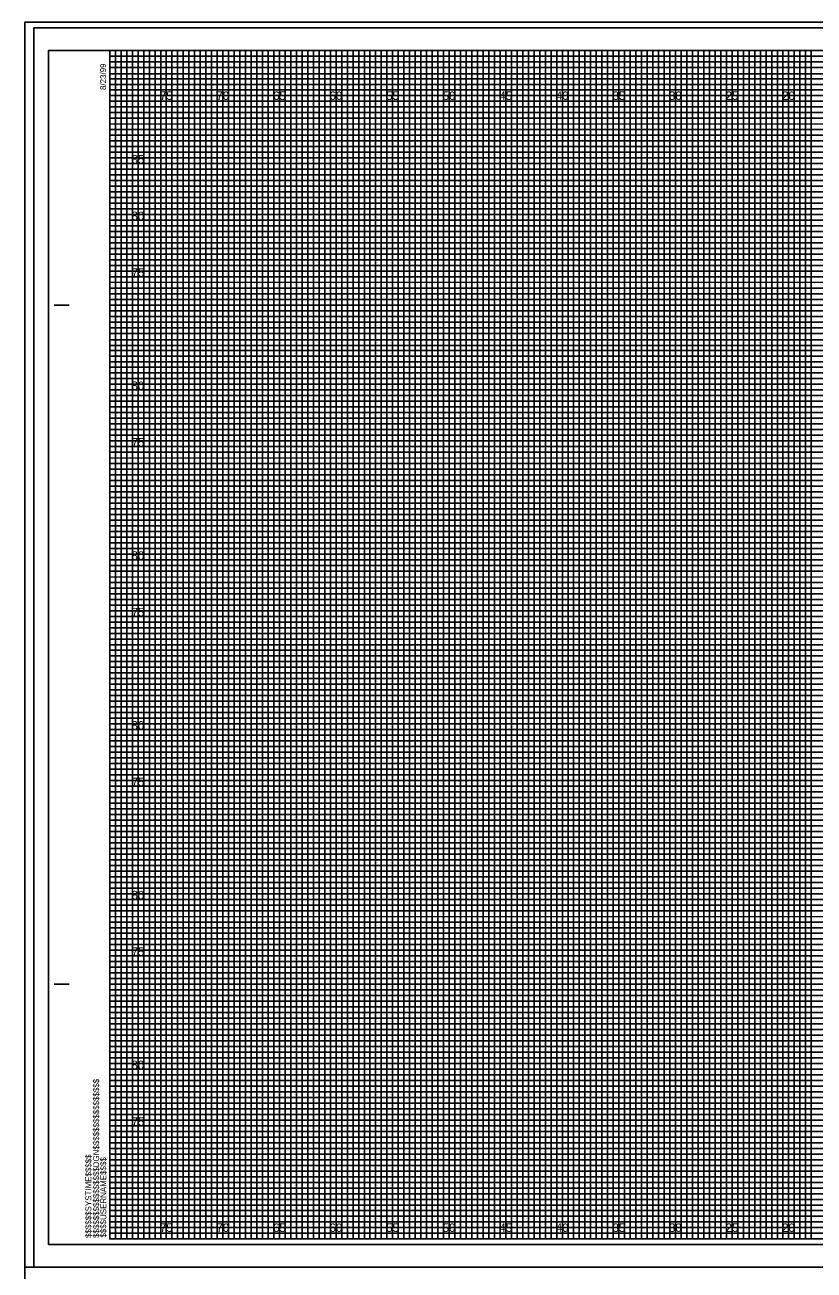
# Model space of a CAD drawing. Extents: x -8 to 533, y -20 to 768.
# Drawn here: x -7.5 to 62.2, y 217.2 to 327.2 of the extents above; entities that cross this region are included whole.
import ezdxf

# ---------------------------------------------------------------- set-up
doc = ezdxf.new("R2010")
doc.units = 0
for name, color, linetype in [('Prop XS Elevation Labels', 7, 'Continuous'), ('Prop XS Offset Labels', 7, 'Continuous'), ('Sheet Cross Section CELL', 7, 'Continuous'), ('Sheet Cross Section Grid Major CELL', 7, 'Continuous'), ('Sheet Cross Section Grid Middle CELL', 7, 'Continuous'), ('Sheet Cross Section Grid Minor 1 CELL', 7, 'Continuous'), ('Sheet Cross Section Grid Minor 2 CELL', 7, 'Continuous'), ('Sheet Cutting Line CELL', 7, 'Continuous'), ('Sheet DOT Grid CELL', 7, 'Continuous'), ('Sheet Plot Border Inside CELL', 7, 'Continuous'), ('Sheet Plot Border Outside CELL', 7, 'Continuous'), ('WEI Plot Border', 7, 'Continuous')]:
    doc.layers.add(name, color=color, linetype=linetype)

msp = doc.modelspace()

# ---------------------------------------------------------------- linework, layer by layer
at = {"layer": 'Sheet Cross Section CELL'}
for p, q in [((-4.9, 302.5), (-3.65, 302.5)), ((-4.85, 302.5), (-3.6, 302.5)), ((-4.9, 242.5), (-3.65, 242.5)), ((-4.85, 242.5), (-3.6, 242.5)), ((0, 220), (0, 220)), ((0, 220), (0, 220)), ((0, 220), (0, 220)), ((0, 220), (0, 220)), ((0, 220), (0, 220)), ((0, 220), (0, 220)), ((0, 220), (0, 220))]:
    msp.add_line(p, q, dxfattribs=at)
msp.add_lwpolyline([(160, 325), (0, 325), (0, 220), (160, 220)], close=True, dxfattribs=at)
at = {"layer": 'Sheet Cross Section Grid Major CELL'}
for p, q in [((5, 325), (0, 325)), ((5, 220), (5, 325)), ((15, 325), (10, 325)), ((10, 325), (10, 220)), ((15, 220), (15, 325)), ((25, 325), (20, 325)), ((20, 325), (20, 220)), ((25, 220), (25, 325)), ((35, 325), (30, 325)), ((30, 325), (30, 220)), ((35, 220), (35, 325)), ((45, 325), (40, 325)), ((40, 325), (40, 220)), ((45, 220), (45, 325)), ((55, 325), (50, 325)), ((50, 325), (50, 220)), ((55, 220), (55, 325)), ((65, 325), (60, 325)), ((60, 325), (60, 220)), ((10, 220), (5, 220)), ((20, 220), (15, 220)), ((30, 220), (25, 220)), ((40, 220), (35, 220)), ((50, 220), (45, 220)), ((60, 220), (55, 220))]:
    msp.add_line(p, q, dxfattribs=at)
for points in [[(0, 320), (160, 320), (160, 315), (0, 315)], [(0, 310), (160, 310), (160, 305), (0, 305)], [(0, 300), (160, 300), (160, 295), (0, 295)], [(0, 290), (160, 290), (160, 285), (0, 285)], [(0, 280), (160, 280), (160, 275), (0, 275)], [(0, 270), (160, 270), (160, 265), (0, 265)], [(0, 260), (160, 260), (160, 255), (0, 255)], [(0, 250), (160, 250), (160, 245), (0, 245)], [(0, 240), (160, 240), (160, 235), (0, 235)], [(0, 230), (160, 230), (160, 225), (0, 225)]]:
    msp.add_lwpolyline(points, dxfattribs=at)
at = {"layer": 'Sheet Cross Section Grid Middle CELL'}
for points in [[(0, 325), (2.5, 325), (2.5, 220), (7.5, 220), (7.5, 325), (12.5, 325), (12.5, 220), (17.5, 220), (17.5, 325), (22.5, 325), (22.5, 220), (27.5, 220), (27.5, 325), (32.5, 325), (32.5, 220), (37.5, 220), (37.5, 325), (42.5, 325), (42.5, 220), (47.5, 220), (47.5, 325), (52.5, 325), (52.5, 220), (57.5, 220), (57.5, 325), (62.5, 325)], [(0, 322.5), (137.5, 322.5)], [(0, 312.5), (160, 312.5), (160, 317.5), (0, 317.5)], [(0, 302.5), (160, 302.5), (160, 307.5), (0, 307.5)], [(0, 292.5), (160, 292.5), (160, 297.5), (0, 297.5)], [(0, 282.5), (160, 282.5), (160, 287.5), (0, 287.5)], [(0, 272.5), (160, 272.5), (160, 277.5), (0, 277.5)], [(0, 262.5), (160, 262.5), (160, 267.5), (0, 267.5)], [(0, 252.5), (160, 252.5), (160, 257.5), (0, 257.5)], [(0, 242.5), (160, 242.5), (160, 247.5), (0, 247.5)], [(0, 232.5), (160, 232.5), (160, 237.5), (0, 237.5)], [(0, 222.5), (160, 222.5), (160, 227.5), (0, 227.5)]]:
    msp.add_lwpolyline(points, dxfattribs=at)
at = {"layer": 'Sheet Cross Section Grid Minor 1 CELL'}
for p, q in [((0, 324.5), (130, 324.5)), ((130, 323.99), (0, 323.99)), ((0, 323.99), (0, 323.5)), ((0, 323.5), (130, 323.5)), ((130, 322.94), (0, 322.94)), ((0, 322.94), (0, 322)), ((0, 322), (160, 322))]:
    msp.add_line(p, q, dxfattribs=at)
for points in [[(0, 321.5), (135, 321.5), (160, 321.5), (160, 321), (0, 321)], [(0, 320.5), (160, 320.5), (160, 319.5), (0, 319.5)], [(0, 319), (160, 319), (160, 318.5), (0, 318.49)], [(0, 318), (160, 318), (160, 317), (0, 317)], [(0, 316.5), (160, 316.5), (160, 316), (0, 316)], [(0, 315.5), (160, 315.5), (160, 314.5), (0, 314.5)], [(0, 314), (160, 314), (160, 313.5), (0, 313.5)], [(0, 313), (160, 313), (160, 312), (0, 312)], [(0, 311.5), (160, 311.5), (160, 311), (0, 311)], [(0, 310.5), (160, 310.5), (160, 309.5), (0, 309.5)], [(0, 309), (160, 309), (160, 308.5), (0, 308.5)], [(0, 308), (160, 308), (160, 306.98), (160, 306.5), (160, 306), (0, 306)], [(0, 307), (160, 307), (160, 306.5), (0, 306.5)], [(0, 305.5), (160, 305.5), (160, 304.5), (0, 304.51)], [(0, 304.51), (160, 304.5), (160, 304), (0, 304)], [(0, 303.5), (160, 303.5), (160, 303), (0, 303)], [(0, 302), (160, 302), (160, 301.5), (0, 301.5)], [(0, 301), (160, 301), (160, 300.5), (0, 300.5)], [(-0.04, 299.44), (160, 299.44), (160, 298.94), (-0.04, 298.94)], [(0, 298.5), (160, 298.5), (160, 298), (0, 298)], [(0, 297), (160, 297), (160, 296.5), (0, 296.5)], [(0, 296), (160, 296), (160, 295.5), (0, 295.5)], [(0, 294.5), (160, 294.5), (160, 294), (0, 294)], [(0, 293.5), (160, 293.5), (160, 293), (0, 293)], [(0, 292), (160, 292), (160, 291.5), (0, 291.5)], [(0, 291), (160, 291), (160, 290.5), (0, 290.5)], [(0, 289.5), (160, 289.5), (160, 288.99), (0, 289)], [(0, 288.5), (160, 288.5), (160, 288), (0, 288)], [(0, 287), (160, 287), (160, 286.5), (0, 286.5)], [(0, 286), (160, 286), (160, 285.5), (0, 285.5)], [(0, 284.5), (160, 284.5), (160, 284), (0, 284)], [(0, 283.5), (160, 283.5), (160, 283), (0, 283)], [(0, 282), (160, 282), (160, 281.5), (0, 281.5)], [(0, 281), (160, 281), (160, 280.5), (0, 280.5)], [(0, 279.5), (160, 279.5), (160, 279), (0, 279)], [(0, 278.5), (160.03, 278.45), (160, 278), (0, 278)], [(0, 277), (160, 277), (160, 276.5), (0, 276.5)], [(0, 276), (160, 276), (160, 275.5), (0, 275.5)], [(0, 274.5), (160, 274.5), (160, 274), (0, 274)], [(0, 273.5), (160, 273.5), (160, 273), (0, 273)], [(0, 272), (160, 272), (160, 271.5), (0, 271.5)], [(0, 271), (160, 271), (160, 270.5), (0, 270.5)], [(0, 269.5), (160, 269.5), (160, 269), (0, 269)], [(0, 268.5), (160, 268.5), (160, 268), (0, 268)], [(0, 267), (160, 267), (160, 266.5), (0, 266.5)], [(0, 266), (160, 266), (160, 265.5), (0, 265.5)], [(0, 264.5), (160, 264.5), (160, 264), (0, 264)], [(0, 263.5), (160, 263.5), (160, 263), (0, 263)], [(0, 262), (160, 262), (160, 261.5), (0, 261.5)], [(0, 261), (160, 261), (160, 260.5), (0, 260.5)], [(0, 259.5), (160, 259.5), (160, 258.99), (0, 259)], [(0, 258.5), (160, 258.5), (160, 258), (0, 258)], [(0, 257), (160, 257), (160, 256.5), (0, 256.5)], [(0, 256), (160, 256), (160, 255.5), (0, 255.5)], [(0, 254.5), (160, 254.5), (160, 254), (0, 254)], [(0, 253.5), (160, 253.5), (160, 253), (0, 253)], [(0, 252), (160, 252), (160, 251.5), (0, 251.5)], [(0, 251), (160, 251), (160, 250.5), (0, 250.5)], [(0, 249.5), (160, 249.5), (160, 249), (0, 249)], [(0, 248.5), (160.03, 248.46), (160, 248), (0, 248)], [(0, 247), (160, 247), (160, 246.5), (0, 246.5)], [(0, 246), (160, 246), (160, 245.5), (0, 245.5)], [(0, 244.5), (160, 244.5), (160, 244), (0, 244)], [(0, 243.5), (160, 243.5), (160, 243), (0, 243)], [(0, 242), (160, 242), (160, 241.5), (0, 241.5)], [(0, 241), (160, 241), (160, 240.5), (0, 240.5)], [(0, 239.5), (160, 239.5), (160, 239), (0, 239)], [(0, 238.5), (160, 238.5), (160, 238), (0, 238)], [(0, 237), (160, 237), (160, 236.5), (0, 236.5)], [(0, 236), (160, 236), (160, 235.5), (0, 235.5)], [(0, 234.5), (160, 234.5), (160, 234), (0, 234)], [(0, 233.5), (160, 233.5), (160, 233), (0, 233)], [(0, 232), (160, 232), (160, 231.5), (0, 231.5)], [(0, 231), (160, 231), (160, 230.5), (0, 230.5)], [(0, 229.5), (160, 229.5), (160, 229), (0, 229)], [(0, 228.5), (160, 228.5), (160, 228), (0, 228)], [(0, 227), (160, 227), (160, 226.5), (0, 226.5)], [(0, 226), (160, 226), (160, 225.5), (0, 225.5)], [(0, 224.5), (160, 224.5), (160, 224), (0, 224)], [(0, 223.5), (160, 223.5), (160, 223), (0, 223)], [(0, 222), (160, 222), (160, 221.5), (0, 221.5)], [(0, 221), (160, 221), (160, 220.5), (0, 220.5)]]:
    msp.add_lwpolyline(points, dxfattribs=at)
at = {"layer": 'Sheet Cross Section Grid Minor 2 CELL'}
for points in [[(0, 220), (0.5, 220), (0.5, 325), (1, 325), (1, 220)], [(1, 220), (1.5, 220), (1.5, 325), (2, 325), (2, 220)], [(2.5, 220), (3, 220), (3, 325), (3.5, 325), (3.5, 220)], [(3.5, 220), (4, 220), (4, 325), (4.5, 325), (4.5, 220)], [(5, 220), (5.5, 220), (5.5, 325), (6, 325), (6, 220)], [(6, 220), (6.5, 220), (6.5, 325), (7, 325), (7, 220)], [(7.5, 220), (8, 220), (8, 325), (8.5, 325), (8.5, 220)], [(8.5, 220), (9, 220), (9, 325), (9.5, 325), (9.5, 220)], [(10, 220), (10.5, 220), (10.5, 325), (11, 325), (11, 220)], [(11, 220), (11.5, 220), (11.5, 325), (12, 325), (12, 220)], [(12.5, 220), (13, 220), (13, 325), (13.5, 325), (13.5, 220)], [(13.5, 220), (14, 220), (14, 325), (14.5, 325), (14.5, 220)], [(15, 220), (15.5, 220), (15.5, 325), (16, 325), (16, 220)], [(16, 220), (16.5, 220), (16.5, 325), (17, 325), (17, 220)], [(17.5, 220), (18, 220), (18, 325), (18.5, 325), (18.5, 220)], [(18.5, 220), (19, 220), (19, 325), (19.5, 325), (19.5, 220)], [(20, 220), (20.5, 220), (20.5, 325), (21, 325), (21, 220)], [(21, 220), (21.5, 220), (21.5, 325), (22, 325), (22, 220)], [(22.5, 220), (23, 220), (23, 325), (23.5, 325), (23.5, 220)], [(23.5, 220), (24, 220), (24, 325), (24.5, 325), (24.5, 220)], [(25, 220), (25.5, 220), (25.5, 325), (26, 325), (26, 220)], [(26, 220), (26.5, 220), (26.5, 325), (27, 325), (27, 220)], [(27.5, 220), (28, 220), (28, 325), (28.5, 325), (28.5, 220)], [(28.5, 220), (29, 220), (29, 325), (29.5, 325), (29.5, 220)], [(30, 220), (30.5, 220), (30.5, 325), (31, 325), (31, 220)], [(31, 220), (31.5, 220), (31.5, 325), (32, 325), (32, 220)], [(32.5, 220), (33, 220), (33, 325), (33.5, 325), (33.5, 220)], [(33.5, 220), (34, 220), (34, 325), (34.5, 325), (34.5, 220)], [(35, 220), (35.5, 220), (35.5, 325), (36, 325), (36, 220)], [(36, 220), (36.5, 220), (36.5, 325), (37, 325), (37, 220)], [(37.5, 220), (38, 220), (38, 325), (38.5, 325), (38.5, 220)], [(38.5, 220), (39, 220), (39, 325), (39.5, 325), (39.5, 220)], [(40, 220), (40.5, 220), (40.5, 325), (41, 325), (41, 220)], [(41, 220), (41.5, 220), (41.5, 325), (42, 325), (42, 220)], [(42.5, 220), (43, 220), (43, 325), (43.5, 325), (43.5, 220)], [(43.5, 220), (44, 220), (44, 325), (44.5, 325), (44.5, 220)], [(45, 220), (45.5, 220), (45.5, 325), (46, 325), (46, 220)], [(46, 220), (46.5, 220), (46.5, 325), (47, 325), (47, 220)], [(47.5, 220), (48, 220), (48, 325), (48.5, 325), (48.5, 220)], [(48.5, 220), (49, 220), (49, 325), (49.5, 325), (49.5, 220)], [(50, 220), (50.5, 220), (50.5, 325), (51, 325), (51, 220)], [(51, 220), (51.5, 220), (51.5, 325), (52, 325), (52, 220)], [(52.5, 220), (53, 220), (53, 325), (53.5, 325), (53.5, 220)], [(53.5, 220), (54, 220), (54, 325), (54.5, 325), (54.5, 220)], [(55, 220), (55.5, 220), (55.5, 325), (56, 325), (56, 220)], [(56, 220), (56.5, 220), (56.5, 325), (57, 325), (57, 220)], [(57.5, 220), (58, 220), (58, 325), (58.5, 325), (58.5, 220)], [(58.5, 220), (59, 220), (59, 325), (59.5, 325), (59.5, 220)], [(60, 220), (60.5, 220), (60.5, 325), (61, 325), (61, 220)], [(61, 220), (61.5, 220), (61.5, 325), (62, 325), (62, 220)]]:
    msp.add_lwpolyline(points, dxfattribs=at)
at = {"layer": 'Sheet Cutting Line CELL'}
for p, q in [((161.65, 327), (-6.7, 327)), ((-6.7, 327), (-6.7, 217.5)), ((-6.7, 217.5), (161.65, 217.5))]:
    msp.add_line(p, q, dxfattribs=at)
at = {"layer": 'Sheet DOT Grid CELL'}
for p, q in [((5, 220), (5, 325)), ((10, 220), (10, 325)), ((15, 220), (15, 325)), ((20, 220), (20, 325)), ((25, 220), (25, 325)), ((30, 220), (30, 325)), ((35, 220), (35, 325)), ((40, 220), (40, 325)), ((45, 220), (45, 325)), ((50, 220), (50, 325)), ((55, 220), (55, 325)), ((60, 220), (60, 325)), ((0, 320), (160, 320)), ((0, 315), (160, 315)), ((0, 310), (160, 310)), ((0, 305), (160, 305)), ((0, 300), (160, 300)), ((0, 295), (160, 295)), ((0, 290), (160, 290)), ((0, 285), (160, 285)), ((0, 280), (160, 280)), ((0, 275), (160, 275)), ((0, 270), (160, 270)), ((0, 265), (160, 265)), ((0, 260), (160, 260)), ((0, 255), (160, 255)), ((0, 250), (160, 250)), ((0, 245), (160, 245)), ((0, 240), (160, 240)), ((0, 235), (160, 235)), ((0, 230), (160, 230)), ((0, 225), (160, 225))]:
    msp.add_line(p, q, dxfattribs=at)
at = {"layer": 'Sheet Plot Border Inside CELL'}
msp.add_lwpolyline([(-5.4, 219.5), (161.2, 219.5), (161.2, 325), (-5.4, 325)], close=True, dxfattribs=at)
at = {"layer": 'Sheet Plot Border Outside CELL'}
msp.add_lwpolyline([(-6.7, 217.5), (161.65, 217.5), (161.65, 327), (-6.7, 327)], close=True, dxfattribs=at)
at = {"layer": 'WEI Plot Border'}
for points in [[(-7.5, 217.5), (162.5, 217.5), (162.5, 327.5), (-7.5, 327.5)], [(-7.5, 107.5), (162.5, 107.5), (162.5, 217.5), (-7.5, 217.5)]]:
    msp.add_lwpolyline(points, close=True, dxfattribs=at)

# ---------------------------------------------------------------- texts
at = {"layer": 'Prop XS Elevation Labels'}
for s, p in [('85', (1.94, 315)), ('80', (1.93, 310)), ('75', (1.94, 305)), ('80', (1.93, 295)), ('75', (1.94, 290)), ('80', (1.93, 280)), ('75', (1.94, 275)), ('80', (1.93, 265)), ('75', (1.94, 260)), ('80', (1.93, 250)), ('75', (1.94, 245)), ('80', (1.93, 235)), ('75', (1.94, 230))]:
    msp.add_text(s, height=0.75, dxfattribs=at).set_placement(p)
at = {"layer": 'Prop XS Offset Labels'}
for s, p in [('75', (4.44, 320.62)), ('70', (9.43, 320.62)), ('65', (14.44, 320.62)), ('60', (19.43, 320.62)), ('55', (24.44, 320.62)), ('50', (29.43, 320.62)), ('45', (34.44, 320.62)), ('40', (39.43, 320.62)), ('35', (44.44, 320.62)), ('30', (49.43, 320.62)), ('25', (54.44, 320.62)), ('20', (59.43, 320.62)), ('75', (4.44, 220.62)), ('70', (9.43, 220.62)), ('65', (14.44, 220.62)), ('60', (19.43, 220.62)), ('55', (24.44, 220.62)), ('50', (29.43, 220.62)), ('45', (34.44, 220.62)), ('40', (39.43, 220.62)), ('35', (44.44, 220.62)), ('30', (49.43, 220.62)), ('25', (54.44, 220.62)), ('20', (59.43, 220.62))]:
    msp.add_text(s, height=0.75, dxfattribs=at).set_placement(p)
at = {"layer": 'Sheet Cross Section CELL'}
for s, p in [('8/23/99', (-0.33, 321.5)), ('$$$$$$$$$$$$$$$$DGN$$$$$$$$$$$$$$$$', (-0.94, 220.09)), ('$$$$$$SYSTIME$$$$$', (-1.63, 220.09)), ('$$$$USERNAME$$$$', (-0.31, 220.12))]:
    msp.add_text(s, height=0.525, rotation=90, dxfattribs=at).set_placement(p)

doc.saveas('drawing.dxf')
